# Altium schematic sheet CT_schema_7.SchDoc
size 278 x 170 mm
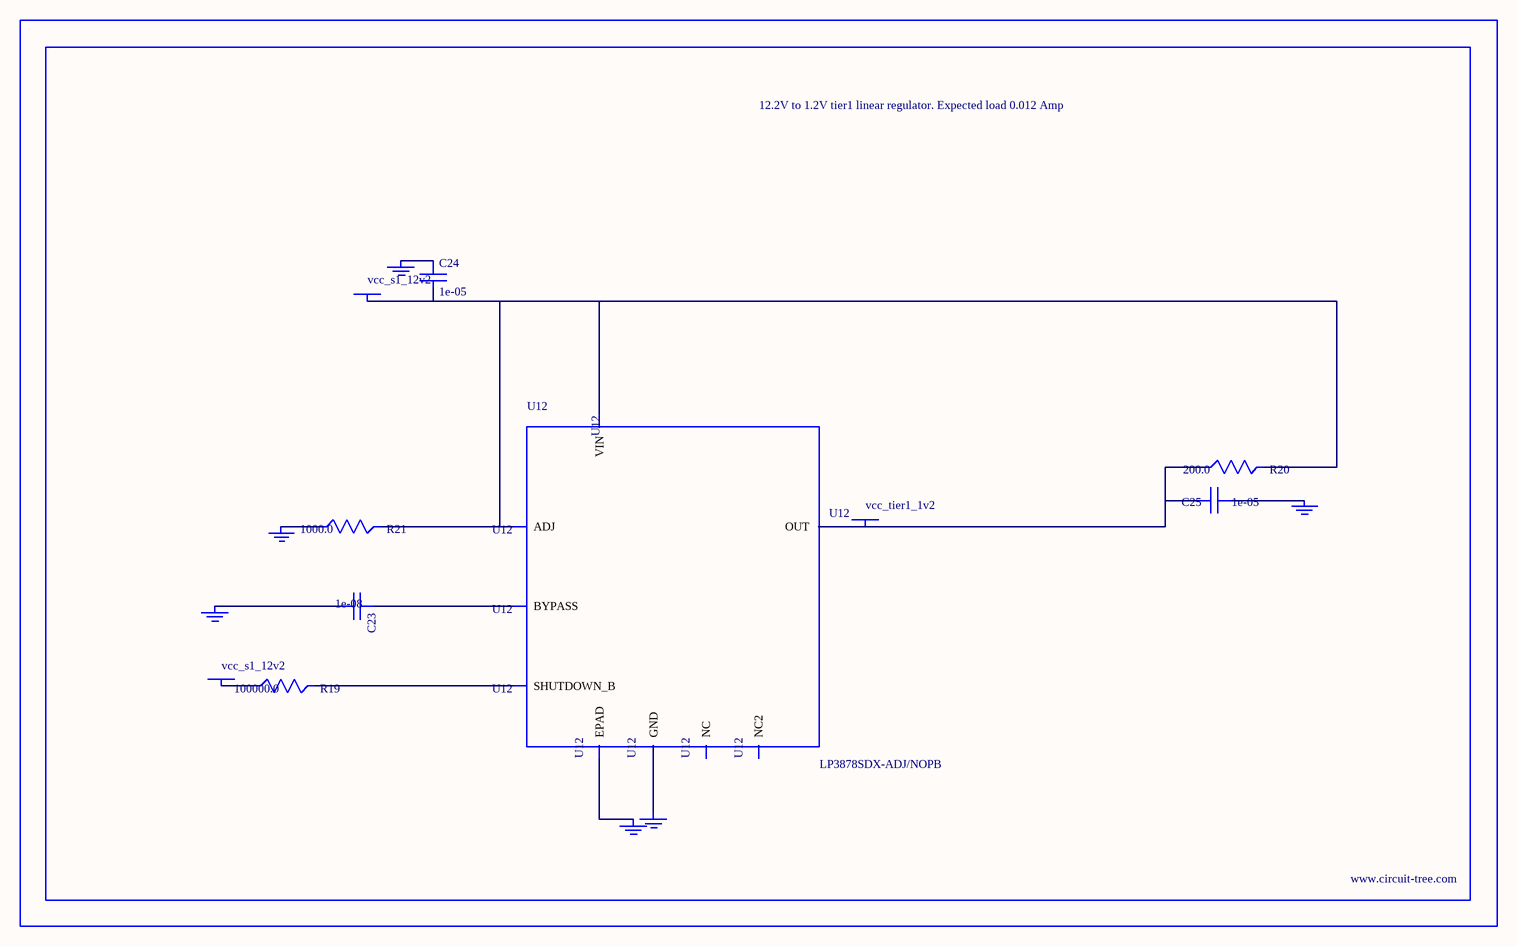
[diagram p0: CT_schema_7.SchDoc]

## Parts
BORDER6  (no value)
C23  1e-08  [C0402]
C24  1e-05  [C1210]
C25  1e-05  [C0805]
GND_INSTANCE_6_0  (no value)
GND_INSTANCE_6_1  (no value)
GND_INSTANCE_6_2  (no value)
GND_INSTANCE_6_3  (no value)
GND_INSTANCE_6_4  (no value)
GND_INSTANCE_6_5  (no value)
POWER_INSTANCE_6_0  vcc_s1_12v2
POWER_INSTANCE_6_1  vcc_s1_12v2
POWER_INSTANCE_6_2  vcc_tier1_1v2
R19  100000.0  [R0603]
R20  200.0  [R0603]
R21  1000.0  [R0603]
U12  LP3878SDX-ADJ/NOPB  [WSON-8]

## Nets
NetC23_1: C23.1 U12.1(BYPASS)
NetC23_2: C23.2 GND_INSTANCE_6_0.0(GND)
NetC24_1: C24.1 GND_INSTANCE_6_1.0(GND)
NetC24_2: C24.2 POWER_INSTANCE_6_0.0(PWR) R20.2 R21.2 U12.4(VIN) U12.6(ADJ)
NetC25_1: C25.1 GND_INSTANCE_6_2.0(GND)
NetC25_2: C25.2 POWER_INSTANCE_6_2.0(PWR) R20.1 U12.5(OUT)
NetGND_INSTANCE_6_3_0: GND_INSTANCE_6_3.0(GND) R21.1
NetGND_INSTANCE_6_4_0: GND_INSTANCE_6_4.0(GND) U12.PAD(EPAD)
NetGND_INSTANCE_6_5_0: GND_INSTANCE_6_5.0(GND) U12.3(GND)
NetPOWER_INSTANCE_6_1_0: POWER_INSTANCE_6_1.0(PWR) R19.1
NetR19_2: R19.2 U12.8(SHUTDOWN_B)

Not connected (* = marked no-connect by the designer): U12 2(NC) 7(NC2)

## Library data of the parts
BORDER6 = BORDER_PAGE6
C23 = C0402C103K3RAC
C24 = C1210C106K5PACTU
C25 = GRM219R60J106ME19D
GND_INSTANCE_6_0-GND_INSTANCE_6_5 = GND
POWER_INSTANCE_6_0-POWER_INSTANCE_6_2 = PWR
R19 = RC0603JR-07100KL
R20 = RC0603JR-07200RL
R21 = RC0603JR-071KL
